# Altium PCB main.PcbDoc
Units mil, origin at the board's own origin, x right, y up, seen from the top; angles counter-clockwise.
Board outline 3149.61 x 1259.84 mil, 2 copper layers (Top Layer, Bottom Layer); 57 components, 46 nets, 238 pads, 73 vias.
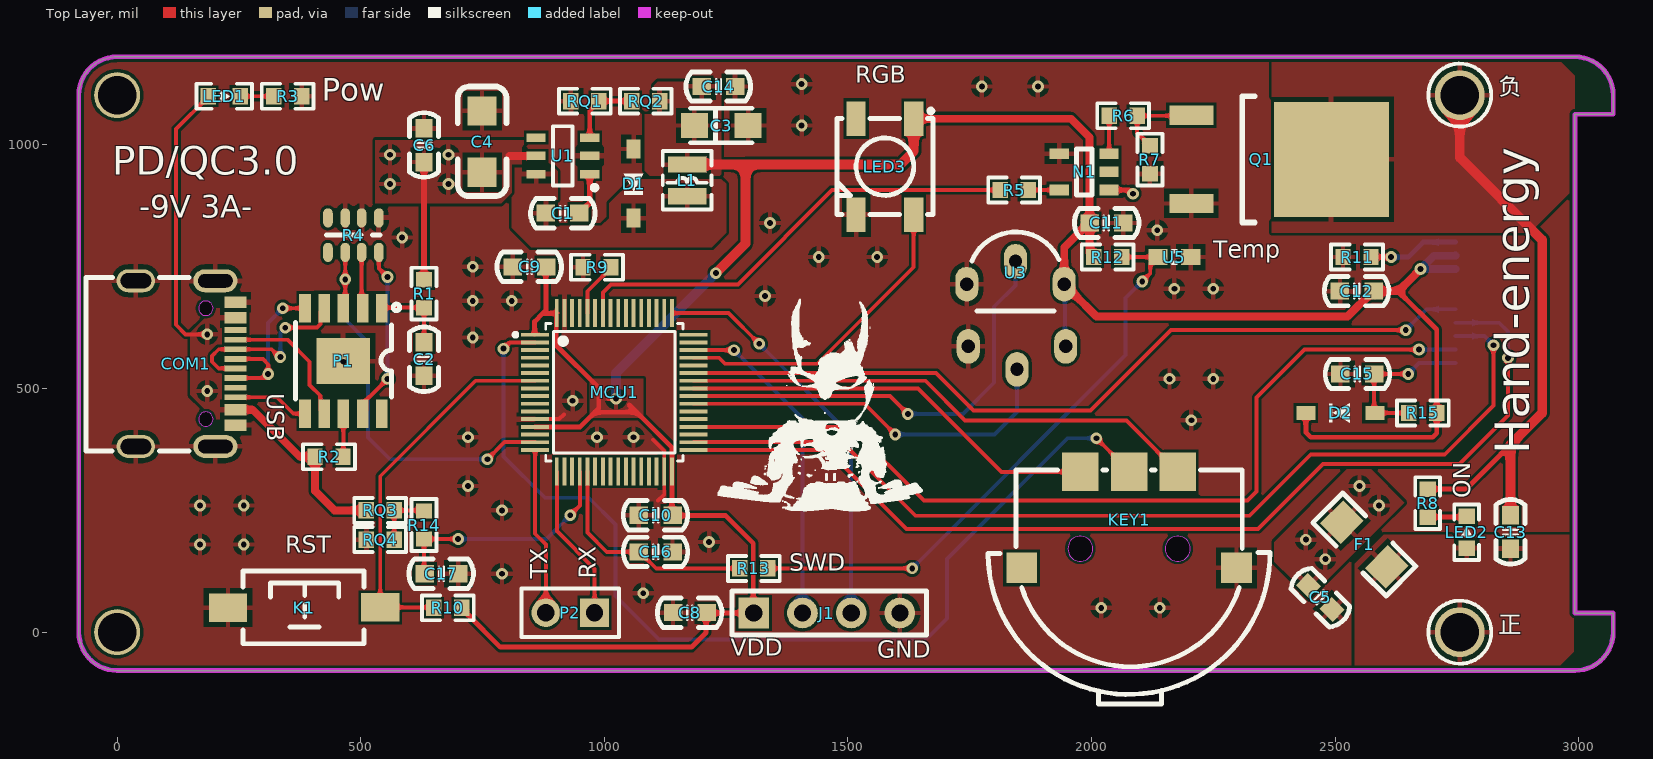
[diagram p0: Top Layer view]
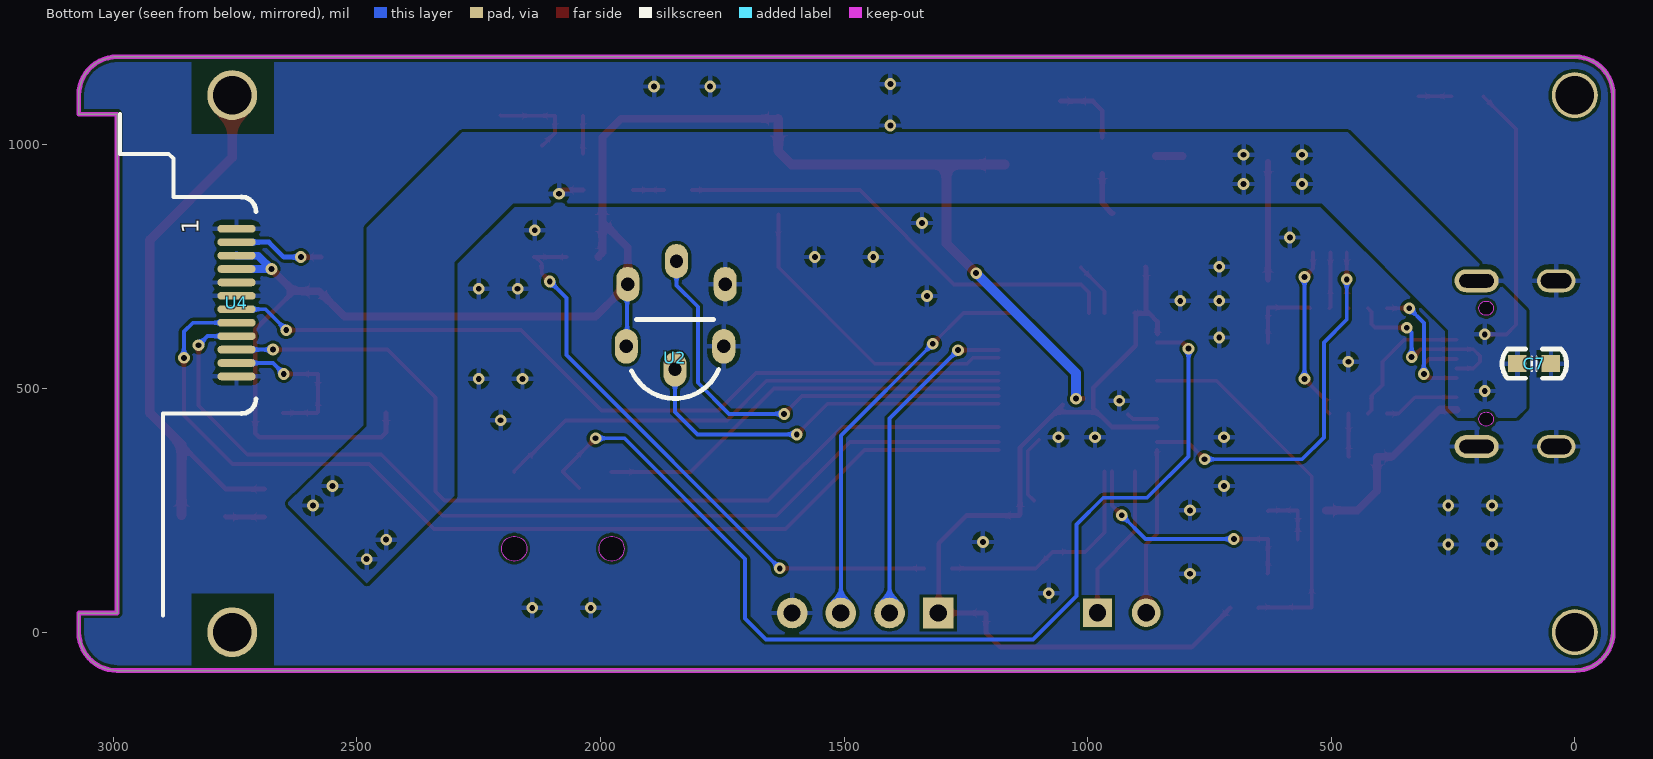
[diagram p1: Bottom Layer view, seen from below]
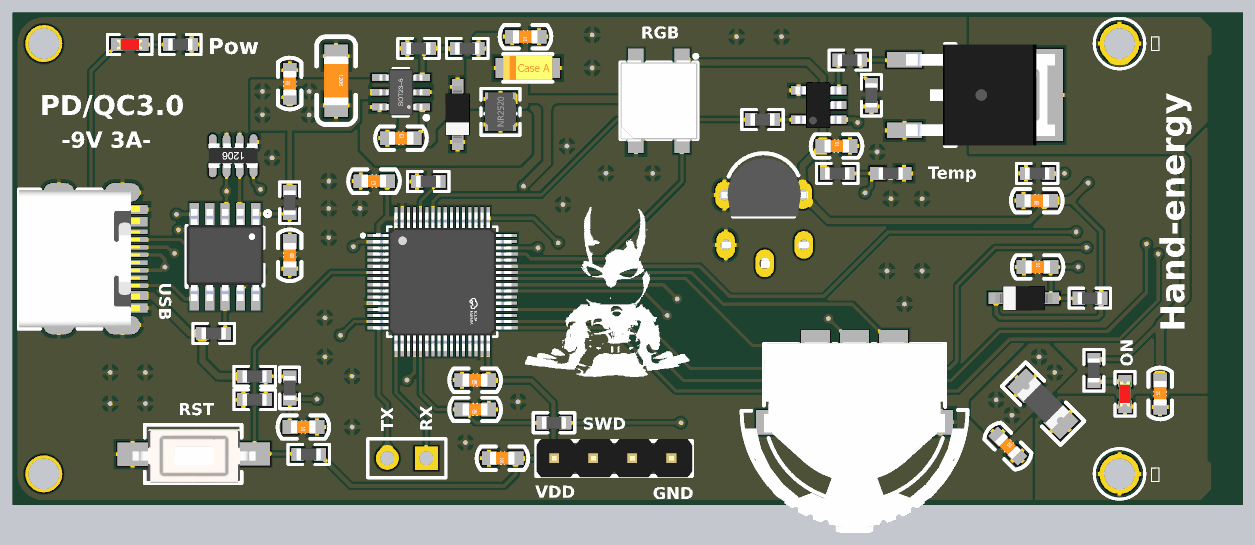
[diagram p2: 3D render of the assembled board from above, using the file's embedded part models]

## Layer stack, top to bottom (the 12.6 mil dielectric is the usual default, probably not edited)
Top Solder: solder mask 0.4, Solder Resist, Dk 3.5
Top Layer: signal copper 1.4
Dielectric 1: dielectric 12.6, FR-4, Dk 4.8
Bottom Layer: signal copper 1.4
Bottom Solder: solder mask 0.4, Solder Resist, Dk 3.5

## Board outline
-78.74,0 -78.74,1102.36 cw(c0,1102.36) 0,1181.1 2992.13,1181.1 cw(c2992.13,1102.36) 3070.87,1102.36 3070.87,1062.99 2992.13,1062.99 2992.13,39.37 3070.87,39.37 3070.87,0 cw(c2992.13,0) 2992.13,-78.74 0,-78.74 cw(c0,0)

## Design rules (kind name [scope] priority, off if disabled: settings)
Clearance [All] p1: gap=6 ignorepadtopadclearanceinfootprint=TRUE
MinimumSolderMaskSliver [All] p1: minsoldermaskwidth=4
PolygonConnect [All] p1: connectstyle=Relief reliefconductorwidth=10 reliefentries=4 polygonreliefangle="90 Angle" airgapwidth=10
RoutingVias [All] p1: holewidth=28 width=50 viastyle="Through Hole" minholewidth=10 minwidth=20 maxholewidth=28 maxwidth=50
SilkToSilkClearance [All] p1: silktosilkclearance=0
SilkToSolderMaskClearance [IsPad] p1: minsilkscreentomaskgap=4 clearancetoexposedcopper=TRUE
SolderMaskExpansion [All] p1: expansion=4 istentingtop=FALSE
Width [All] p1: maxlimit=50 minlimit=6 preferedwidth=10
27 further rules are at their usual default settings.

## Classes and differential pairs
component class Sheet2: C14 C15 C16 C17 D2 R11 R12 R13 R14 R15 RQ3 RQ4 U4 U5
component class Sheet: C1 C2 C3 C4 C5 C6 C7 C8 C9 C10 C11 C12 C13 COM1 D1 F1 J1 K1 KEY1 L1 LED1 LED2 LED3 MCU1 N1 P1 P2 Q1 R1 R2 R3 R4 R5 R6 R7 R8 R9 R10 RQ1 RQ2 U1 U2 U3

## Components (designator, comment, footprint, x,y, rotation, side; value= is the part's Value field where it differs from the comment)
C1 "10NF" CAP_0603 880,860 r0 top
C2 "100NF" CAP_0603 630,595 r270 top
C3 "22UF" CAP_3216_A 1240,1040 r180 top
C4 "22UF" CAP_1206 750,1070 r270 top
C5 "100NF" CAP_0603 2445.14,95.79 r315 top
C6 "100NF" CAP_0603 630,965 r90 top
C7 "100NF" CAP_0603 118.11,551.18 r180 bottom
C8 "100NF" CAP_0603 1210,40 r180 top
C9 "100NF" CAP_0603 881,750 r180 top
C10 "100NF" CAP_0603 1140,240 r180 top
C11 "100NF" CAP_0603 1996,840 r0 top
C12 "100NF" CAP_0603 2579,700 r180 top
C13 "100NF" CAP_0603 2860,171 r90 top
C14 "4.7uF" CAP_0603 1269,1120 r180 top
C15 "4.7uF" CAP_0603 2511,530 r0 top
C16 "100NF" CAP_0603 1140,165 r180 top
C17 "100NF" CAP_0603 700,120 r180 top
COM1 "Type-C" USB-TYPE-C_16A 39.37,551.18 r270 top
D1 "B5819W" DIODE_SOD123 1060,991.73 r270 top
D2 "1N4148" DIODE_SOD123 2581.73,450 r180 top
F1 "FUSE" FUSE_1206 2560,180 r135 top
J1 "P4" "Header 2.54X4" 1456.69,39.37 r0 top
K1 "KEY" KEY-A 385,50 r0 top
KEY1 "KEY" KEY-K1-1502SA-LY-K3 2297.47,132.13 r180 top
L1 "2.2UH" INDUCTANCE_NR 1170,895.04 r180 top
LED1 "LED_R/G/B/Y" LED_0603_R 220,1100 r180 top
LED2 "LED_R/G/B/Y" LED_0603_R 2770,205 r270 top
LED3 "WS2812B" WS2812B 1635,1054 r270 top
MCU1 "AT32F415RCT7" LQFP64P-7 858,610.5 r0 top
N1 "U?" SOT23_5 1985,945 r0 top
P1 "CH224K" ESSOP_10 543.11,665 r270 top
P2 "Header 2" HDR1X2 980,40 r180 top
Q1 "MOS_N" TO252_2 2425.47,970.55 r0 top
R1 "1K" RESC_0603_2 630,695 r90 top
R2 "10K" RESC_0603_2 435,360 r180 top
R3 "10K" RESC_0603_2 350,1100 r0 top
R4 "10K" RESC_0603_4 485,815 r180 top
R5 "1K" RESC_0603_2 1841.26,907.6 r180 top
R6 "10Ω" RESC_0603_2 2065,1060 r180 top
R7 "10K" RESC_0603_2 2120,970 r270 top
R8 "10K" RESC_0603_2 2690,265 r90 top
R9 "10K" RESC_0603_2 985,749 r180 top
R10 "10K" RESC_0603_2 678.74,50 r180 top
R11 "30Ω" RESC_0603_2 2545,770 r0 top
R12 "6.8K" RESC_0603_2 2033,770 r0 top
R13 "1K" RESC_0603_2 1307,131 r180 top
R14 "1K" RESC_0603_2 630,220 r270 top
R15 "4.7K" RESC_0603_2 2680,450 r0 top
RQ1 "19.6k" RESC_0603_2 960,1090 r0 top
RQ2 "62k" RESC_0603_2 1085,1090 r180 top
RQ3 "10k" RESC_0603_2 540,250 r180 top
RQ4 "1.5k" RESC_0603_2 540,190 r0 top
U1 "RT8259" SOT-23-6 970,940.2 r180 top
U2 "DS18B20" TO_92B 1847,563 r0 bottom
U3 "DS18B20" TO_92B 1844,738 r0 top
U4 "TFT_1.3_12Pin" LCD_1.3_Pad 2747,828.12 r90 bottom locked
U5 "Temper" RESC_0603_1 2170,770 r0 top

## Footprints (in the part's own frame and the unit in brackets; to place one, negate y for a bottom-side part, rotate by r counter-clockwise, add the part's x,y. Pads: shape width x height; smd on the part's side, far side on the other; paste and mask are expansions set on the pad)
CAP_0603 [mil]
  rect 38x35 smd: 1(0,0) 2(69,0)
  silkscreen extent -31,-30 101,30, body extent 4,-16 67,16, height 12
CAP_1206 [mil]
  rect 60x60 smd: 1(0,-1) 2(126,-1)
  silkscreen extent -50,-51 175,49, body extent 0,-32 126,31, height 39
CAP_3216_A [mm]
  rect 1.4x1.3 smd: 1(1.4,0) 2(-1.4,0)
  silkscreen extent -1.6,-0.9 1.6,0.9, body extent -1.6,-0.8 1.6,0.8, height 1.6
DIODE_SOD123 [mm]
  rect 1x0.75 smd: 1(0,0) 2(3.6,0)
  silkscreen extent 1.3,-0.5 2.4,0.5, body extent -0.05,-0.8 3.65,0.8, height 1.27
ESSOP_10 [mm]
  rect 1.5x0.6 smd mask+0.051: 1(0,0) 2(0,-1) 3(0,-2) 4(0,-3) 5(0,-4) 6(5.5,-4) 7(5.5,-3) 8(5.5,-2) 9(5.5,-1) 10(5.5,0)
  rect 2.4x2.8 smd mask+0.051: 11(2.75,-2)
  silkscreen extent -0.21,-4.5 4.75,0.94, body extent -0.35,-4.5 5.65,0.5, height 1.9
FUSE_1206 [mm]
  rect 1.524x1.7 smd: 1(-1.65,0) 2(1.65,0)
  silkscreen extent -2.7,-1.1 2.7,1.1, body extent -1.6,-0.85 1.6,0.8, height 1.43
HDR1X2 [mm] "Connector; Header; 2 Position"
  rect 1.5x1.5 hole 0.9: 1(0,0)
  round 1.5 hole 0.9: 2(2.54,0)
  silkscreen extent -1.27,-1.27 3.81,1.27
"Header 2.54X4" [mm]
  rect 1.6x1.6 hole 0.9: 1(-3.81,0)
  round 1.6 hole 0.9: 2(-1.27,0) 3(1.27,0) 4(3.81,0)
  silkscreen extent -4.95,-1.14 5.19,1.14, body extent -4.95,-1.23 5.21,1.27, height 8.3
INDUCTANCE_NR [mm]
  rect 2x0.85 smd: 1(0,0) 2(0,-1.65)
  silkscreen extent -1.27,-2.35 1.27,0.7, body extent -1,-2.07 1,0.43, height 1.1
KEY-A [mm]
  rect 2x1.5 smd: 1(-3.996,0.005) 2(3.937,0.025)
  silkscreen extent -3.21,-1.87 3.09,1.93, body extent -4,-1.85 4,1.65, height 2.59
KEY-K1-1502SA-LY-K3 [mil]
  rect 63x63 smd mask+2: 0(440.95,0) 1(0,0)
  rect 74.8x78.74 smd mask+2: 2(120.47,-196.87) 3(220.47,-196.87) 4(320.47,-196.87)
  Keep-Out Layer board cut-out: 346.07,-39.4 343.54,-28.29 336.44,-19.39 326.17,-14.44 314.78,-14.44 304.51,-19.39 297.41,-28.29 294.87,-39.4 294.87,-39.4 297.41,-50.51 304.51,-59.41 314.78,-64.36 326.17,-64.36 336.44,-59.41 343.54,-50.51 346.07,-39.4
  Keep-Out Layer board cut-out: 146.07,-39.4 143.54,-28.29 136.44,-19.39 126.17,-14.44 114.78,-14.44 104.51,-19.39 97.41,-28.29 94.87,-39.4 94.87,-39.4 97.41,-50.51 104.51,-59.41 114.78,-64.36 126.17,-64.36 136.44,-59.41 143.54,-50.51 146.07,-39.4
  silkscreen extent -69,-201 510,280, body extent -65,-205 506,285, height 102
LCD_1.3_Pad [mm]
  oval 0.4x2 smd: 1(0,0) 2(-0.7,0) 3(-1.4,0) 4(-2.1,0) 5(-2.8,0) 6(-3.5,0) 7(-4.2,0) 8(-4.9,0) 9(-5.6,0) 10(-6.3,0) 11(-7,0) 12(-7.7,0)
  silkscreen extent -20.17,-1.01 5.99,6.07
LED_0603_R [mm]
  rect 0.8x0.85 smd: 1(-0.832,0) 2(0.832,0)
  silkscreen extent -1.45,-0.65 1.45,0.65, body extent -0.81,-0.4 0.81,0.4, height 0.6
LQFP64P-7 [mil]
  rect 57.5x7.9 smd mask+2: 1(0,0) 2(0,-15.7) 3(0,-31.5) 4(0,-47.2) 5(0,-63) 6(0,-78.7) 7(0,-94.5) 8(0,-110.2) 9(0,-126) 10(0,-141.7) 11(0,-157.5) 12(0,-173.2) 13(0,-189) 14(0,-204.7) 15(0,-220.5) 16(0,-236.2) 33(325.2,-236.2) 34(325.2,-220.5) 35(325.2,-204.7) 36(325.2,-189) 37(325.2,-173.2) 38(325.2,-157.5) 39(325.2,-141.7) 40(325.2,-126) 41(325.2,-110.2) 42(325.2,-94.5) 43(325.2,-78.7) 44(325.2,-63) 45(325.2,-47.2) 46(325.2,-31.5) 47(325.2,-15.7) 48(325.2,0)
  rect 7.9x57.5 smd mask+2: 17(44.5,-280.7) 18(60.2,-280.7) 19(76,-280.7) 20(91.7,-280.7) 21(107.5,-280.7) 22(123.2,-280.7) 23(139,-280.7) 24(154.7,-280.7) 25(170.5,-280.7) 26(186.2,-280.7) 27(202,-280.7) 28(217.7,-280.7) 29(233.5,-280.7) 30(249.2,-280.7) 31(265,-280.7) 32(280.7,-280.7) 49(280.7,44.5) 50(265,44.5) 51(249.2,44.5) 52(233.5,44.5) 53(217.7,44.5) 54(202,44.5) 55(186.2,44.5) 56(170.5,44.5) 57(154.7,44.5) 58(139,44.5) 59(123.2,44.5) 60(107.5,44.5) 61(91.7,44.5) 62(76,44.5) 63(60.2,44.5) 64(44.5,44.5)
  silkscreen extent -44,-259 303,23, body extent -15,-295 340,59, height 50
RESC_0603_1 [mm]
  rect 1x0.85 smd: 1(-0.857,0) 2(0.857,0)
  silkscreen extent -0.1,-0.3 0.1,0.3, body extent -0.8,-0.4 0.8,0.4, height 0.38
RESC_0603_2 [mm]
  rect 0.8x0.85 smd: 1(-0.73,0) 2(0.73,0)
  silkscreen extent -1.35,-0.65 1.35,0.65, body extent -0.8,-0.4 0.8,0.4, height 0.38
RESC_0603_4 [mm]
  oval 0.5x1 smd: 1(-1.327,-0.9) 2(-1.327,0.9) 3(-0.425,-0.9) 4(-0.425,0.9) 5(0.425,-0.9) 6(0.425,0.9) 7(1.327,-0.9) 8(1.327,0.9)
  silkscreen extent -1.4,0 1.4,0, body extent -1.6,-0.8 1.6,0.8, height 0.5
SOT23_5 [mm]
  rect 1x0.55 smd: 1(1.3,-0.95) 2(1.3,0) 3(1.3,0.95) 4(-1.3,0.95) 5(-1.3,-0.95)
  silkscreen extent -0.4,-1.21 0.4,1.19, body extent -1.52,-1.51 1.48,1.49, height 1.3
SOT-23-6 [mm]
  rect 1x0.45 smd: 1(0,0) 2(0,-0.95) 3(0,-1.9) 4(2.794,-1.9) 5(2.794,-0.95) 6(2.794,0)
  silkscreen extent -0.38,-2.5 1.91,0.82, body extent -0.01,-2.45 2.8,0.55, height 1.15
TO252_2 [mm]
  rect 2.3x1 smd: 1(-5.6,2.3) 2(-5.6,-2.3)
  rect 6x6 smd: 3(1.7,0)
  silkscreen extent -2.95,-3.29 -2.29,3.29, body extent -5.5,-3.29 4.2,3.29, height 2.3
TO_92B [mm]
  oval 1.2x1.8 hole 0.7: 1(-2.54,-0.6) 2(0,0.6) 3(2.54,-0.6)
  silkscreen extent -2.28,-2 2.27,2.12, body extent -2.8,-2 2.88,1.8, height 7.34
USB-TYPE-C_16A [mm]
  oval 1.199x2.301 hole 0.701 slot 1.801 at 90 deg mask+0.051: 0(-4.32,4.123) 0(4.321,4.123)
  oval 1.199x1.999 hole 0.8 slot 1.6 at 90 deg mask+0.051: 0(-4.32,-0.025) 0(4.321,-0.025)
  round 0 hole 0.65: 0(-2.889,3.592) 0(2.891,3.592)
  rect 0.3x1.151 smd mask+0.05: A5(-1.249,5.179) A6(-0.248,5.177) A7(0.25,5.177) A8(-1.749,5.177) B5(1.751,5.177) B6(0.75,5.177) B7(-0.749,5.177) B8(1.25,5.177)
  rect 0.599x1.151 smd mask+0.05: A9(-2.4,5.174) A12(-3.2,5.174) B1(3.201,5.177) B4(2.401,5.177)
  Keep-Out Layer board cut-out: -2.514,3.625 -2.551,3.788 -2.655,3.919 -2.806,3.991 -2.973,3.991 -3.124,3.919 -3.229,3.788 -3.266,3.625 -3.266,3.625 -3.229,3.462 -3.124,3.331 -2.973,3.258 -2.806,3.258 -2.655,3.331 -2.551,3.462 -2.514,3.625
  Keep-Out Layer board cut-out: 3.267,3.625 3.23,3.788 3.126,3.919 2.975,3.991 2.808,3.991 2.657,3.919 2.553,3.788 2.515,3.625 2.515,3.625 2.553,3.462 2.657,3.331 2.808,3.258 2.975,3.258 3.126,3.331 3.23,3.462 3.267,3.625
  silkscreen extent -4.5,-2.63 4.56,2.75, body extent -4.47,-2.63 4.47,5.27, height 3.25
WS2812B [mil] "5050"
  rect 70.9x39.4 smd mask+2: 1(0,0) 2(0,-118.1) 3(196.8,-118.1) 4(196.8,0)
  silkscreen extent -20,-158 197,39, body extent -6,-158 203,39, height 63

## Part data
C1 C2 C4 C5 C6 C7 C8 C9 C10 C11 C12 C13 C14 C15 C16 C17: library part CAP, "CAP  12~50V"
C3: library part CAP_TA, "CAP  6~12V  钽电容"
COM1: library part USB-type_c, "USB"
D1 D2: library part Diode-SM, "Diode_肖特基/二极管"
J1: library part SWD, "Header"
K1: "Key"
KEY1: library part LY-K3
L1: library part Inductor, "Inductor"
LED1 LED2: library part LED_SMT, "LED"
LED3: "LED"
MCU1: "MCU"
N1: library part N531, "栅极控制器，18V"
P1: "PD\QC"
P2: "Header, 2-Pin"
Q1: library part MOSFET_N, "MOS"
R1 R2 R3 R5 R6 R7 R8 R9 R10 R11 R12 R13 R14 R15: library part RES, "RES 贴片"
R4: library part RES_P4, "RES"
RQ1 RQ2 RQ3 RQ4: library part RES_quality, "RES"
U1: "DC-DC"
U2 U3: "MODE"
U4: library part "LCD_1.3   T", "ST7789V-SPI"
U5: "Mode"

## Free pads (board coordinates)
  round 94.49 hole 78.74: 0(0,0) 0(0,1102.36)
  round 102.36 hole 78.74: 1(2755.91,1102.36) 2(2755.91,0)

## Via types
v1: diameter 24, hole 12, Top Layer to Bottom Layer, tented both sides, 73 vias

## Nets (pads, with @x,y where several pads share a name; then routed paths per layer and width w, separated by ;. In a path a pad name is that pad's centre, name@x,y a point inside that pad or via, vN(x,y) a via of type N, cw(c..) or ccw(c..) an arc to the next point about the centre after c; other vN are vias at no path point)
ADC_Temp: C16.2 MCU1.21 R13.2 | length 468.5
  Top Layer w8: MCU1.21 965.5,204.5 1005,165 C16.2 1072.5,165 1106.5,131 R13.2
ADC_Vol: C17.2 MCU1.20 R14.2 | length 489.8
  Top Layer w8: C17.2 630,121 R14.2 v1(700,191.26) ; v1(930,240) 930,240.2 949.7,259.9 MCU1.20
  Bottom Layer w8: v1(700,191.26) 881.26,191.26 v1(930,240)
BOOT0: MCU1.60 R9.1 | length 114
  Top Layer w8: MCU1.60 965.5,699.78 1013.74,748.02 R9.1
CC1: COM1.A5 P1.7 | length 289.5
  Top Layer w8: COM1.A5 349.65,600.35 395,555 395,507.5 417.19,485.31 417.19,456.28 P1.7
CC2: COM1.B5 P1.6 | length 156.4
  Top Layer w8: COM1.B5 327.75,482.25 361.53,448.47 P1.6
CFG3: MCU1.15 P1.3 R4.6 | length 835.9
  Top Layer w8: P1.3 468.25,668.88 v1(468.25,724.22) R4.6 ; v1(760,355) 795,390 MCU1.15
  Bottom Layer w8: v1(468.25,724.22) 468.25,641.75 515,595 515,400 560,355 v1(760,355)
D/C: MCU1.43 U4.7 | length 1681.7
  Top Layer w8: MCU1.43 1681,531.8 1757.8,455 1998,455 2163,620 v1(2645,620)
  Bottom Layer w8: v1(2645,620) 2687.76,662.76 U4.7
DN: COM1.A7 COM1.B7 P1.4 | length 393.3
  Top Layer w8: COM1.A7 208.65,541.35 195,555 195,567.01 208.65,580.65 COM1.B7 316.71,580.65 332.37,565 v1(335,565) ; v1(345,625) 410,625 417.19,632.19 417.19,657.19 P1.4
  Bottom Layer w8: v1(335,565) 335,615 v1(345,625)
DP: COM1.A6 COM1.B6 P1.5 | length 354.7
  Top Layer w8: COM1.B6 301.65,521.65 v1(310,530) 310,550 299.05,560.95 COM1.A6 ; v1(340,665) P1.5
  Bottom Layer w8: v1(310,530) 310,635 v1(340,665)
GND: C2.2 C3.2 C4.1 C5.2 C6.2 C7.2 C8.2 C9.2 C10.2 C11.2 C12.2 C14.1 C15.1 C16.1 C17.1 COM1.0@38.38,381.05 COM1.0@38.38,721.25 COM1.0@201.68,381.05 COM1.0@201.68,721.25 COM1.A12 COM1.B1 D1.1 J1.4 K1.1 KEY1.1 LED3.3 MCU1.12 MCU1.31 MCU1.63 N1.4 P1.11 Q1.2 R3.2 R4.1 R4.3 R4.5 R7.2 R9.2 R11.1 RQ1.1 RQ4.1 U1.2 U2.1 U3.1 U4.1 U4.5 U4.6 U4.12 U5.2 | length 202.9
  Top Layer w8: MCU1.12 907.3,437.3 916.95,446.95 ; 1100,395 1123,372 MCU1.31 1123,283 1110,270
  other v1: 2020,50 2140,50 1080,80 790,120 170,180 260,180 1215,185 790,250 170,260 260,260 720,300 720,400 985,400 1060,400 2205,435 935,475 2160,520 2250,520 465,555 730,605 730,680 810,680 1330,690 2170,705 2250,705 730,750 1440,770 1560,770 585,810 2135,825 1340,840 1405,1040 1775,1120 1890,1120 1405,1125
IO_D1: MCU1.39 U2.2 | length 796.3
  Top Layer w8: MCU1.39 1534.2,468.8 v1(1597.09,405.91)
  Bottom Layer w8: v1(1597.09,405.91) 1800.91,405.91 1847,452 U2.2
IO_D2: MCU1.40 U3.2 | length 926.3
  Top Layer w8: MCU1.40 1586.5,484.5 v1(1623,448)
  Bottom Layer w8: v1(1623,448) 1736,448 1800,512 1800,668 1844,712 U3.2
KEY1: KEY1.2 MCU1.42 | length 1072.4
  Top Layer w8: MCU1.42 1659,516 1740.5,434.5 2071.5,434.5 2141.63,364.37 2143.6,364.37 2177,330.97 KEY1.2
KEY2: KEY1.3 MCU1.2 | length 2136.7
  Top Layer w8: v1(793,582) 805.8,594.8 MCU1.2 ; v1(2009.97,398) 2077,330.97 KEY1.3 KEY1.3@2043.6,295.6
  Bottom Layer w8: v1(793,582) 793,361 878,276 968,276 1023,221 1023,74 1112,-15 1660,-15 1703,28 1703,150 1951,398 v1(2009.97,398)
KEY3: KEY1.4 MCU1.41 | length 864.8
  Top Layer w8: MCU1.41 1643.7,500.3 1815,329 KEY1.4
LED: LED3.4 MCU1.45 | length 647.1
  Top Layer w8: MCU1.45 1235.7,563.3 1248,551 1437,551 1635,749 LED3.4
MISO: MCU1.35
MOSI: MCU1.36 U4.10 | length 1868.1
  Top Layer w8: MCU1.36 1504.5,421.5 1656,270 2320,270 2339,289 2339,482 2437.09,580.09 v1(2672.09,580.09)
  Bottom Layer w8: v1(2672.09,580.09) U4.10
NetC1_1: C1.1 D1.2 L1.1 U1.6
NetC1_2: C1.2 U1.1 | length 89.8
  Top Layer w12: C1.2 950.5,860 962,871.5 962,873 970,881 U1.1
NetC2_1: C2.1 P1.1 R1.1 | length 158.7
  Top Layer w8: P1.1 544.37,666.26 R1.1 C2.1
NetLED1_1: LED1.1 R3.1 | length 68.5
  Top Layer w8: LED1.1 R3.1
NetLED2_1: LED2.1 R8.1 | length 80.6
  Top Layer w10: R8.1 2768.52,236.26 LED2.1
NetN1_3: N1.3 R6.2 | length 77.6
  Top Layer w8: N1.3 2036.26,982.48 R6.2
NetN1_5: N1.5 R5.1 | length 63.8
  Top Layer w8: R5.1 N1.5
NetP1_2: P1.2 R4.4 | length 115.4
  Top Layer w8: R4.4 501.75,666.99 P1.2
NetP1_8: P1.8 R2.1 | length 88.7
  Top Layer w8: R2.1 464.37,360.63 P1.8
NetP1_9: P1.9 R4.2 | length 365.7
  Top Layer w8: P1.9 511.55,456.28 511.55,476.55 v1(555,520) ; R4.2 537.24,746.76 v1(555,729)
  Bottom Layer w8: v1(555,520) v1(555,729) v1@555,735
NetQ1_1: Q1.1 R6.1 R7.1 | length 184.4
  Top Layer w8: R7.1 2119.02,998.74 2107.27,1010.49 2107.27,1011.47 2093.74,1025 R6.1 2203.9,1060 Q1.1
NetR11_2: R11.2 U4.2 | length 185.9
  Top Layer w10: R11.2 v1(2615,770)
  Bottom Layer w10: v1(2615,770) 2650,770 2680.56,800.56 U4.2
NetR12_2: R12.2 R13.1 U5.1 | length 1209.2
  Top Layer w8: R13.1 v1(1632,131) ; R12.2@2070,770 U5.1@2133.31,770 ; v1(2104,720) 2120.57,736.57 2120.57,757.27 U5.1@2133.31,770 ; U5.1 U5.1@2133.31,770
  Bottom Layer w8: v1(1632,131) 2070,569 2070,686 v1(2104,720)
NetR14_1: R14.1 RQ3.1 RQ4.2 | length 121.8
  Top Layer w8: RQ4.2 RQ3.1 628.74,250 R14.1
NetRQ1_2: RQ1.2 RQ2.2 U1.3 | length 150.3
  Top Layer w10: U1.3 970,1070.28 988.74,1089.02 RQ1.2 RQ2.2
NSS: MCU1.33 U4.8 | length 2123.1
  Top Layer w8: MCU1.33 1457.7,374.3 1620,212 2342,212 2475,345 2755,345 2855,445 v1(2855,563)
  Bottom Layer w8: U4.8 2836.8,635.2 2855,617 v1(2855,563)
OUT: C13.2 pad.1 Q1.3 R8.2 | length 1167.1
  Top Layer w10: R8.2 2768.74,293.74 2860,385
  Top Layer w20: pad.1 2755.91,974.09 2925,805 2925,450 2860,385 C13.2
OUT+: C13.1 F1.1 LED2.2 pad.2
PWM: MCU1.58 R5.2 | length 944.8
  Top Layer w8: MCU1.58 997,697 1014,714 1274,714 1467.6,907.6 R5.2
RES: C15.2 D2.1 R15.1 U4.11 | length 326.6
  Top Layer w8: v1(2650,530) C15.2 2580,451.73 D2.1 R15.1
  Bottom Layer w8: v1(2650,530) 2672.53,552.53 U4.11
RST: K1.2 MCU1.7 R10.2 | length 778.6
  Top Layer w8: R10.2 649,51 K1.2 540,320 736,516 MCU1.7
SCLK: MCU1.34 U4.9 | length 2007.7
  Top Layer w8: MCU1.34 1488,390 1639,239 2324,239 2450,365 2725,365 2825,465 v1(2825,589)
  Bottom Layer w8: U4.9 2806.35,607.65 v1(2825,589)
SWDIO: J1.2 MCU1.46 | length 680.7
  Top Layer w8: MCU1.46 v1(1266,579)
  Bottom Layer w8: v1(1266,579) 1406.69,438.31 J1.2
SWSCK: J1.3 MCU1.49 | length 836.2
  Top Layer w8: MCU1.49 1255,655 v1(1318,592)
  Bottom Layer w8: v1(1318,592) 1506.69,403.31 J1.3
UART2_RX: MCU1.17 P2.1 | length 321.9
  Top Layer w8: MCU1.17 902.5,207.5 980,130 P2.1
UART2_TX: MCU1.16 P2.2 | length 343.4
  Top Layer w8: MCU1.16 858,202 880,180 P2.2
VCC: C4.2 C5.1 C6.1 C7.1 COM1.A9 COM1.B4 F1.2 LED1.2 N1.1 R1.2 R2.2 RQ3.2 U1.5 | length 1311.7
  Top Layer w8: v1(184.9,611.31) 140.69,611.31 121,631 121,1032.76 187.26,1099.02 LED1.2
  Top Layer w10: N1.1 2077.4,907.6 v1(2085,900)
  Top Layer w12: R1.2 C6.1
  Top Layer w16: COM1.B4 278.35,456.65 375,360 R2.2 406.26,290 446.26,250 RQ3.2 ; 805,977 805.6,977.6 U1.5
  other v1: 2480,150 2440,190 2590,260 2550,300 185,495 560,920 680,920 560,980 680,980
VDD: C3.1 C8.1 C9.1 C10.1 C11.1 C12.1 C14.2 D2.2 J1.1 L1.2 LED3.1 MCU1.1 MCU1.13 MCU1.32 MCU1.64 R10.1 R12.1 R15.2 RQ2.1 U2.3 U3.3 U4.3 U4.4 | length 5575.5
  Top Layer w10: R10.1 718.23,39.25 718.23,37.58 786.44,-30.63 1178.96,-30.63 1208.96,-0.63 1208.96,38.96 C8.1 1210.63,39.37 J1.1 1305.65,40.41 1305.65,182.68 1248.96,239.37 1140.63,239.37 C10.1 1138.7,241.3 MCU1.32 1138.7,379.3 1066.5,451.5 ; MCU1.1@856.96,611.55 856.96,637.37 873.96,654.37 ; MCU1.13 950.5,421.5 980.5,451.5 ; C9.1 879.96,748.96 879.96,660.37 873.96,654.37 ; MCU1.64@901.45,654.37 873.96,654.37 ; MCU1.64 901.46,653.96 901.46,588.54 988.5,501.5 988.5,459.5 980.5,451.5 ; 1008.96,479.37 v1(1023.96,479.37) v1@1027.75,479.37 ; 1051.09,466.91 1066.5,451.5 ; D2.2 2440,410 2450,400 2700,400 2708.74,408.74 R15.2 2708.74,621.26 2630,700 ; 980.5,451.5 1066.5,451.5
  Top Layer w16: LED3.1 1958,1054 1996,1016 C11.1 ; R12.1 2004.26,770.98 1996,779.24 C11.1 ; v1(2675.44,745.44) 2630,700 C12.1 2577.5,700 2525.5,648 2010.38,648 1961.79,696.59 1958.43,696.59 1944,711.02 U3.3 1944,789.5 1994.5,840 C11.1
  Top Layer w20: L1.2 1290,960 ; v1(1229,737) 1290,798 1290,960 ; LED3.1 1635,987 1608,960 1290,960
  Bottom Layer w8: U3.3 1945.5,712.88 1945.5,588.12 U2.3
  Bottom Layer w16: U4.4 v1(2675.44,745.44) 2702.87,772.87 2746.87,772.87 U4.3
  Bottom Layer w20: v1(1023.96,479.37) 1023.96,531.96 v1(1229,737)
pads on no net: COM1.0@180.8,437.36 COM1.0@180.8,664.92 COM1.A8 COM1.B8 KEY1.0 LED3.2 MCU1.3 MCU1.4 MCU1.5 MCU1.6 MCU1.8 MCU1.9 MCU1.10 MCU1.11 MCU1.14 MCU1.18 MCU1.19 MCU1.22 MCU1.23 MCU1.24 MCU1.25 MCU1.26 MCU1.27 MCU1.28 MCU1.29 MCU1.30 MCU1.37 MCU1.38 MCU1.44 MCU1.47 MCU1.48 MCU1.50 MCU1.51 MCU1.52 MCU1.53 MCU1.54 MCU1.55 MCU1.56 MCU1.57 MCU1.59 MCU1.61 MCU1.62 N1.2 P1.10 R4.7 R4.8 U1.4

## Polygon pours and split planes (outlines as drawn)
GND on Top Layer "GND_L01_P015" (solid, remove dead copper, pour order 15): -236.22,1377.95 3188.98,1377.95 3188.98,-354.33 -236.22,-354.33
OUT on Top Layer "OUT_L01_P010" (solid, remove dead copper, pour order 10): 2370,1180 2650,1180 2953.86,1180 2992.12,1141.74 2992.12,912.12 2900,820 2370,820
VCC on Top Layer "VCC_L01_P014" (solid, remove dead copper, pour order 14): 2524,334 2375,185 2375,145 2448,72 2642,266 2574,334
OUT+ on Top Layer "OUT+_L01_P012" (solid, remove dead copper, pour order 12): 2600,200 2540,140 2540,-70 2960,-70 2990,-40 2990,200
VDD on Top Layer "VDD_L01_P007" (solid, remove dead copper, pour order 7): 1083,1103 1110,1130 1240,1130 1240,940 1230,930 1100,930 1083,947
VDD on Top Layer "VDD_L01_P008" (solid, pour order 8): 970,520 1080,520 1080,440 970,440
NetC1_1 on Top Layer "NETC1_1_L01_P005" (solid, remove dead copper, pour order 5): 810,960 890,960 904,946 904,834 994,834 1010,850 1010,880 1060,930 1240,930 1250,920 1250,820 1220,790 850,790 810,830
VCC on Top Layer "VCC_L01_P004" (solid, remove dead copper, pour order 4): 530,1010 880,1010 890,1000 890,960 810,960 810,902 788,880 530,880
VCC on Top Layer "VCC_L01_P002" (solid, remove dead copper, pour order 2): 275.73,665 200,665 150,615 150,487.17 199.87,437.31 275.83,437.31 275.83,664.9
GND on Bottom Layer "GND_L02_P016" (solid, remove dead copper, pour order 16): -237.68,1449.88 3345,1449.88 3345,-439.88 -237.68,-439.88
VCC on Bottom Layer "VCC_L02_P009" (solid, pour order 9): 710,1026 2284,1026 2479.67,830.33 2479.67,422.37 2643.17,263.83 2479.67,100.33 2300,280 2300,759 2179,880 710,880
VCC on Bottom Layer "VCC_L02_P003" (solid, remove dead copper, pour order 3): 100,460 120,440 240,440 260,460 260,620 520,880 780,880 820,920 820,1026 466,1026 240,800 100,660

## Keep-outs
Keep-Out Layer:
  the board outline again, w10

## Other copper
Bottom Layer:
  pour cut-out: 2670,1180 2840,1180 2840,1022.36 2670,1022.36
  pour cut-out: 2670,-77.64 2840,-77.64 2840,80 2670,80

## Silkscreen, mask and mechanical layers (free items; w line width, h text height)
Top Overlay:
  drawing of 1425 lines, arcs and shapes, not listed
  text "RGB" at 1515,1115.55 h60
  text "负" at 2835,1091.22 h60
  text "Pow" at 420,1075.74 h80
  text "PD/QC3.0" at -10,919.43 h100
  text "-9V 3A-" at 45.07,835.74 h80
  text "Temp" at 2250,756.27 h60
  text "USB" at 295.55,490 h60 r270
  text "Hand-energy" at 2922,365 h120 r90
  text "ON" at 2789.45,275.06 h60 r90
  text "RST" at 345,150.56 h60
  text "SWD" at 1380.06,113.56 h60
  text "TX" at 895,110.06 h60 r90
  text "RX" at 995,110 h60 r90
  text "正" at 2835.06,-13.48 h60
  text "VDD" at 1259,-61 h60
  text "GND" at 1560.06,-64.44 h60
Mechanical 15:
  lines w10: 0,-78.74 0,1181.1 ; 2755.91,0 2992.13,0 ; 2755.91,1102.36 2992.13,1102.36
  text "SIZE-70*28MM" at 0.11,1251.09 h118.11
